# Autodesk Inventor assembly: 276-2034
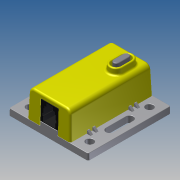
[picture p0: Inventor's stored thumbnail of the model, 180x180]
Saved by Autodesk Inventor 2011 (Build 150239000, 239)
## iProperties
Company: Autodesk Inc.
Created: 2010-06
Part Number: 276-2034
Document SubType Name: Assembly
Designer: Autodesk Inc.
Catalog Web Link: http://www.vexrobotics.com/276-2034.html
Description: Commands are entered through the joysticks and buttons on the RF Transmitter, and sent through the air via FM radio waves to th
Vendor: Innovation First, Inc.
Author: Autodesk Inc.
Title: VEX Robotics Kit of Parts
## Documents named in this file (5)
- C:\Data Folder\VEX KOP 2010\VEX Receiver Module.iam
- C:\Data Folder\VEX KOP 2010\VEX Receiver Module Bottom.ipt
- C:\Data Folder\VEX KOP 2010\VEX Receiver Module Top.ipt
- C:\Data Folder\VEX KOP 2010\VEX Receiver Jack.ipt
- C:\Data Folder\VEX KOP 2010\VEX Receiver Module Crystal.ipt
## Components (4 placed, 4 different names)
1. VEX Receiver Module Bottom:1 — Mate:1, Mate:2, Flush:1, Mate:3, Angle:1
2. VEX Receiver Module Top:1 — Mate:1, Mate:2, Flush:1, Flush:2, Flush:3, Mate:4
3. VEX Receiver Jack:1 — Mate:3, Flush:2, Angle:1
4. VEX Receiver Module Crystal:1 — Flush:3, Mate:4
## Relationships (8: Mate 4, Flush 3, Angle 1)
- Mate:1: VEX Receiver Module Bottom:1 ↔ VEX Receiver Module Top:1
- Mate:2: VEX Receiver Module Bottom:1 ↔ VEX Receiver Module Top:1
- Flush:1: VEX Receiver Module Bottom:1 ↔ VEX Receiver Module Top:1
- Mate:3: VEX Receiver Module Bottom:1 ↔ VEX Receiver Jack:1
- Flush:2: VEX Receiver Module Top:1 ↔ VEX Receiver Jack:1
- Angle:1: VEX Receiver Module Bottom:1 ↔ VEX Receiver Jack:1
- Flush:3: VEX Receiver Module Top:1 ↔ VEX Receiver Module Crystal:1
- Mate:4: VEX Receiver Module Top:1 ↔ VEX Receiver Module Crystal:1
